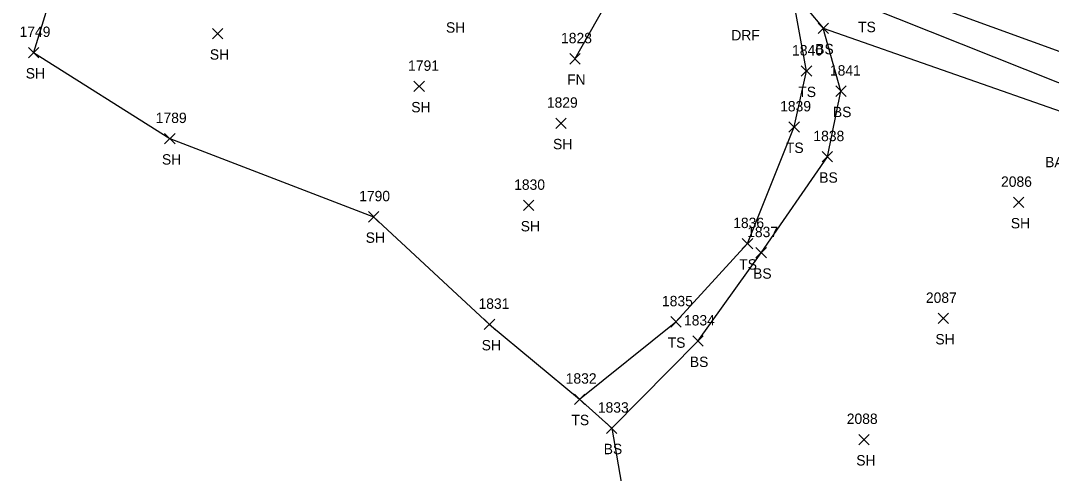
# Model space of a CAD drawing. Extents: x 1459992 to 1461532, y 647785 to 648535.
# Drawn here: x 1460919.3 to 1461117.9, y 648201.4 to 648288.6 of the extents above; entities that cross this region are included whole.
import ezdxf

# ---------------------------------------------------------------- set-up
doc = ezdxf.new("R2010")
doc.units = 0
for name, color, linetype in [('L_A', 7, 'Continuous'), ('L_I', 7, 'Continuous'), ('L_TIC', 7, 'Continuous'), ('LELB', 7, 'Continuous'), ('LFNC', 7, 'Continuous'), ('LSOGP', 7, 'Continuous'), ('PET', 7, 'Continuous'), ('R_A', 7, 'Continuous'), ('S_C', 7, 'Continuous')]:
    doc.layers.add(name, color=color, linetype=linetype)

msp = doc.modelspace()

# ---------------------------------------------------------------- linework, layer by layer
at = {"layer": 'L_TIC'}
for points in [[(1461072.92, 648286.11), (1461074.92, 648288.11)], [(1461074.92, 648286.11), (1461072.92, 648288.11)], [(1461072.92, 648286.11), (1461074.92, 648288.11)], [(1461074.92, 648286.11), (1461072.92, 648288.11)], [(1460956.3, 648285.07), (1460958.3, 648287.07)], [(1460958.3, 648285.07), (1460956.3, 648287.07)], [(1460920.84, 648281.44), (1460922.84, 648283.44)], [(1460922.84, 648281.44), (1460920.84, 648283.44)], [(1461025.11, 648280.23), (1461027.11, 648282.23)], [(1461027.11, 648280.23), (1461025.11, 648282.23)], [(1461069.7, 648277.87), (1461071.7, 648279.87)], [(1461071.7, 648277.87), (1461069.7, 648279.87)], [(1460995.1, 648274.93), (1460997.1, 648276.93)], [(1460997.1, 648274.93), (1460995.1, 648276.93)], [(1461076.34, 648274), (1461078.34, 648276)], [(1461078.34, 648274), (1461076.34, 648276)], [(1461022.4, 648267.82), (1461024.4, 648269.82)], [(1461024.4, 648267.82), (1461022.4, 648269.82)], [(1461067.32, 648267.11), (1461069.32, 648269.11)], [(1461069.32, 648267.11), (1461067.32, 648269.11)], [(1460947.08, 648264.87), (1460949.08, 648266.87)], [(1460949.08, 648264.87), (1460947.08, 648266.87)], [(1461073.71, 648261.38), (1461075.71, 648263.38)], [(1461075.71, 648261.38), (1461073.71, 648263.38)], [(1461110.55, 648252.59), (1461112.55, 648254.59)], [(1461112.55, 648252.59), (1461110.55, 648254.59)], [(1461016.17, 648252.01), (1461018.17, 648254.01)], [(1461018.17, 648252.01), (1461016.17, 648254.01)], [(1460986.32, 648249.81), (1460988.32, 648251.81)], [(1460988.32, 648249.81), (1460986.32, 648251.81)], [(1461058.33, 648244.65), (1461060.33, 648246.65)], [(1461060.33, 648244.65), (1461058.33, 648246.65)], [(1461060.97, 648242.9), (1461062.97, 648244.9)], [(1461062.97, 648242.9), (1461060.97, 648244.9)], [(1461008.65, 648229.1), (1461010.65, 648231.1)], [(1461010.65, 648229.1), (1461008.65, 648231.1)], [(1461044.55, 648229.6), (1461046.55, 648231.6)], [(1461046.55, 648229.6), (1461044.55, 648231.6)], [(1461096.03, 648230.25), (1461098.03, 648232.25)], [(1461098.03, 648230.25), (1461096.03, 648232.25)], [(1461048.79, 648225.9), (1461050.79, 648227.9)], [(1461050.79, 648225.9), (1461048.79, 648227.9)], [(1461026.01, 648214.7), (1461028.01, 648216.7)], [(1461028.01, 648214.7), (1461026.01, 648216.7)], [(1461032.2, 648209.12), (1461034.2, 648211.12)], [(1461034.2, 648209.12), (1461032.2, 648211.12)], [(1461080.79, 648206.94), (1461082.79, 648208.94)], [(1461082.79, 648206.94), (1461080.79, 648208.94)]]:
    msp.add_lwpolyline(points, dxfattribs=at)
at = {"layer": 'LELB'}
for points in [[(1460941.15, 648349.78), (1460973.92, 648337.2), (1461015.24, 648321.11), (1461040.67, 648310.01), (1461064.18, 648298.16), (1461082.22, 648291.36), (1461125.02, 648274.34), (1461150.75, 648265.39), (1461172.28, 648256.95), (1461198.57, 648246.42), (1461223, 648236.28), (1461241.79, 648231.37), (1461257.62, 648226.89), (1461266.9, 648221.63), (1461276.01, 648214.68), (1461281.47, 648211.06), (1461286.34, 648210.46)], [(1460939.64, 648344.38), (1460971.19, 648332.05), (1461013, 648314.77), (1461039.31, 648304.76), (1461062.9, 648294.47), (1461067.87, 648294.36), (1461073.92, 648287.11), (1461122.33, 648270.19), (1461146.57, 648259.51), (1461168.44, 648252.02), (1461196.41, 648241.56), (1461220.18, 648231.28), (1461239.03, 648226.47), (1461251, 648216.36), (1461259.3, 648208.22), (1461262.9, 648204.94)], [(1461027.01, 648215.7), (1461045.55, 648230.6), (1461059.33, 648245.65), (1461068.32, 648268.11), (1461070.7, 648278.87), (1461067.87, 648294.36)], [(1461033.2, 648210.12), (1461049.79, 648226.9), (1461061.97, 648243.9), (1461074.71, 648262.38), (1461077.34, 648275), (1461073.92, 648287.11)]]:
    msp.add_lwpolyline(points, dxfattribs=at)
at = {"layer": 'LFNC'}
msp.add_lwpolyline([(1460991.77, 648320.92), (1461037.89, 648302.09), (1461026.11, 648281.23)], dxfattribs=at)
at = {"layer": 'LSOGP'}
msp.add_lwpolyline([(1460928.43, 648303.96), (1460921.84, 648282.44), (1460948.08, 648265.87), (1460987.32, 648250.81), (1461009.65, 648230.1), (1461027.01, 648215.7), (1461033.2, 648210.12), (1461043.65, 648149.58)], dxfattribs=at)
at = {"layer": 'PET'}
msp.add_lwpolyline([(1460942.85, 648353.98), (1460975.34, 648340.07), (1461016.08, 648323.29), (1461041.44, 648312.66), (1461070.03, 648301.09), (1461083.95, 648295.62), (1461128.85, 648279.26), (1461164.21, 648269.58), (1461178.63, 648262.65), (1461203.09, 648251.99), (1461227.86, 648243.02), (1461244.86, 648238.13), (1461258.8, 648233.38), (1461270.23, 648226.19), (1461279.65, 648219.62), (1461287.61, 648211.81)], dxfattribs=at)

# ---------------------------------------------------------------- texts
at = {"layer": 'L_A'}
for s, p in [('SH', (1461001.26, 648286.27)), ('TS', (1461080.63, 648286.36)), ('BS', (1461072.37, 648282.11)), ('BS', (1461072.37, 648282.11)), ('SH', (1460955.79, 648281.07)), ('SH', (1460920.33, 648277.44)), ('FN', (1461024.59, 648276.23)), ('TS', (1461069.11, 648273.87)), ('SH', (1460994.58, 648270.93)), ('BS', (1461075.78, 648270)), ('SH', (1461021.88, 648263.82)), ('TS', (1461066.73, 648263.11)), ('SH', (1460946.56, 648260.87)), ('BS', (1461073.15, 648257.38)), ('SH', (1461110.04, 648248.59)), ('SH', (1461015.66, 648248.01)), ('SH', (1460985.8, 648245.81)), ('TS', (1461057.74, 648240.65)), ('BS', (1461060.41, 648238.9)), ('SH', (1461008.14, 648225.1)), ('TS', (1461043.96, 648225.6)), ('SH', (1461095.52, 648226.25)), ('BS', (1461048.23, 648221.9)), ('TS', (1461025.42, 648210.7)), ('BS', (1461031.64, 648205.12)), ('SH', (1461080.28, 648202.94))]:
    msp.add_text(s, height=2, dxfattribs=at).set_placement(p)
at = {"layer": 'L_I'}
for s, p in [('1749', (1460919.14, 648285.44)), ('1828', (1461023.42, 648284.23)), ('1840', (1461067.92, 648281.87)), ('1791', (1460993.97, 648278.93)), ('1841', (1461075.21, 648278)), ('1829', (1461020.69, 648271.82)), ('1839', (1461065.62, 648271.11)), ('1789', (1460945.37, 648268.87)), ('1838', (1461072.02, 648265.38)), ('2086', (1461108.16, 648256.59)), ('1830', (1461014.39, 648256.01)), ('1790', (1460984.54, 648253.81)), ('1836', (1461056.58, 648248.65)), ('1837', (1461059.27, 648246.9)), ('2087', (1461093.69, 648234.25)), ('1831', (1461007.53, 648233.1)), ('1835', (1461042.86, 648233.6)), ('1834', (1461047.1, 648229.9)), ('1832', (1461024.32, 648218.7)), ('1833', (1461030.51, 648213.12)), ('2088', (1461078.45, 648210.94))]:
    msp.add_text(s, height=2, dxfattribs=at).set_placement(p)
at = {"layer": 'R_A'}
msp.add_text('DRF', height=2, dxfattribs=at).set_placement((1461056.21, 648284.78))
at = {"layer": 'S_C'}
msp.add_text('BARRIED TEL CABLE', height=2, dxfattribs=at).set_placement((1461116.65, 648260.35))

doc.saveas('drawing.dxf')
